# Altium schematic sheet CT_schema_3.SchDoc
size 572 x 500 mm
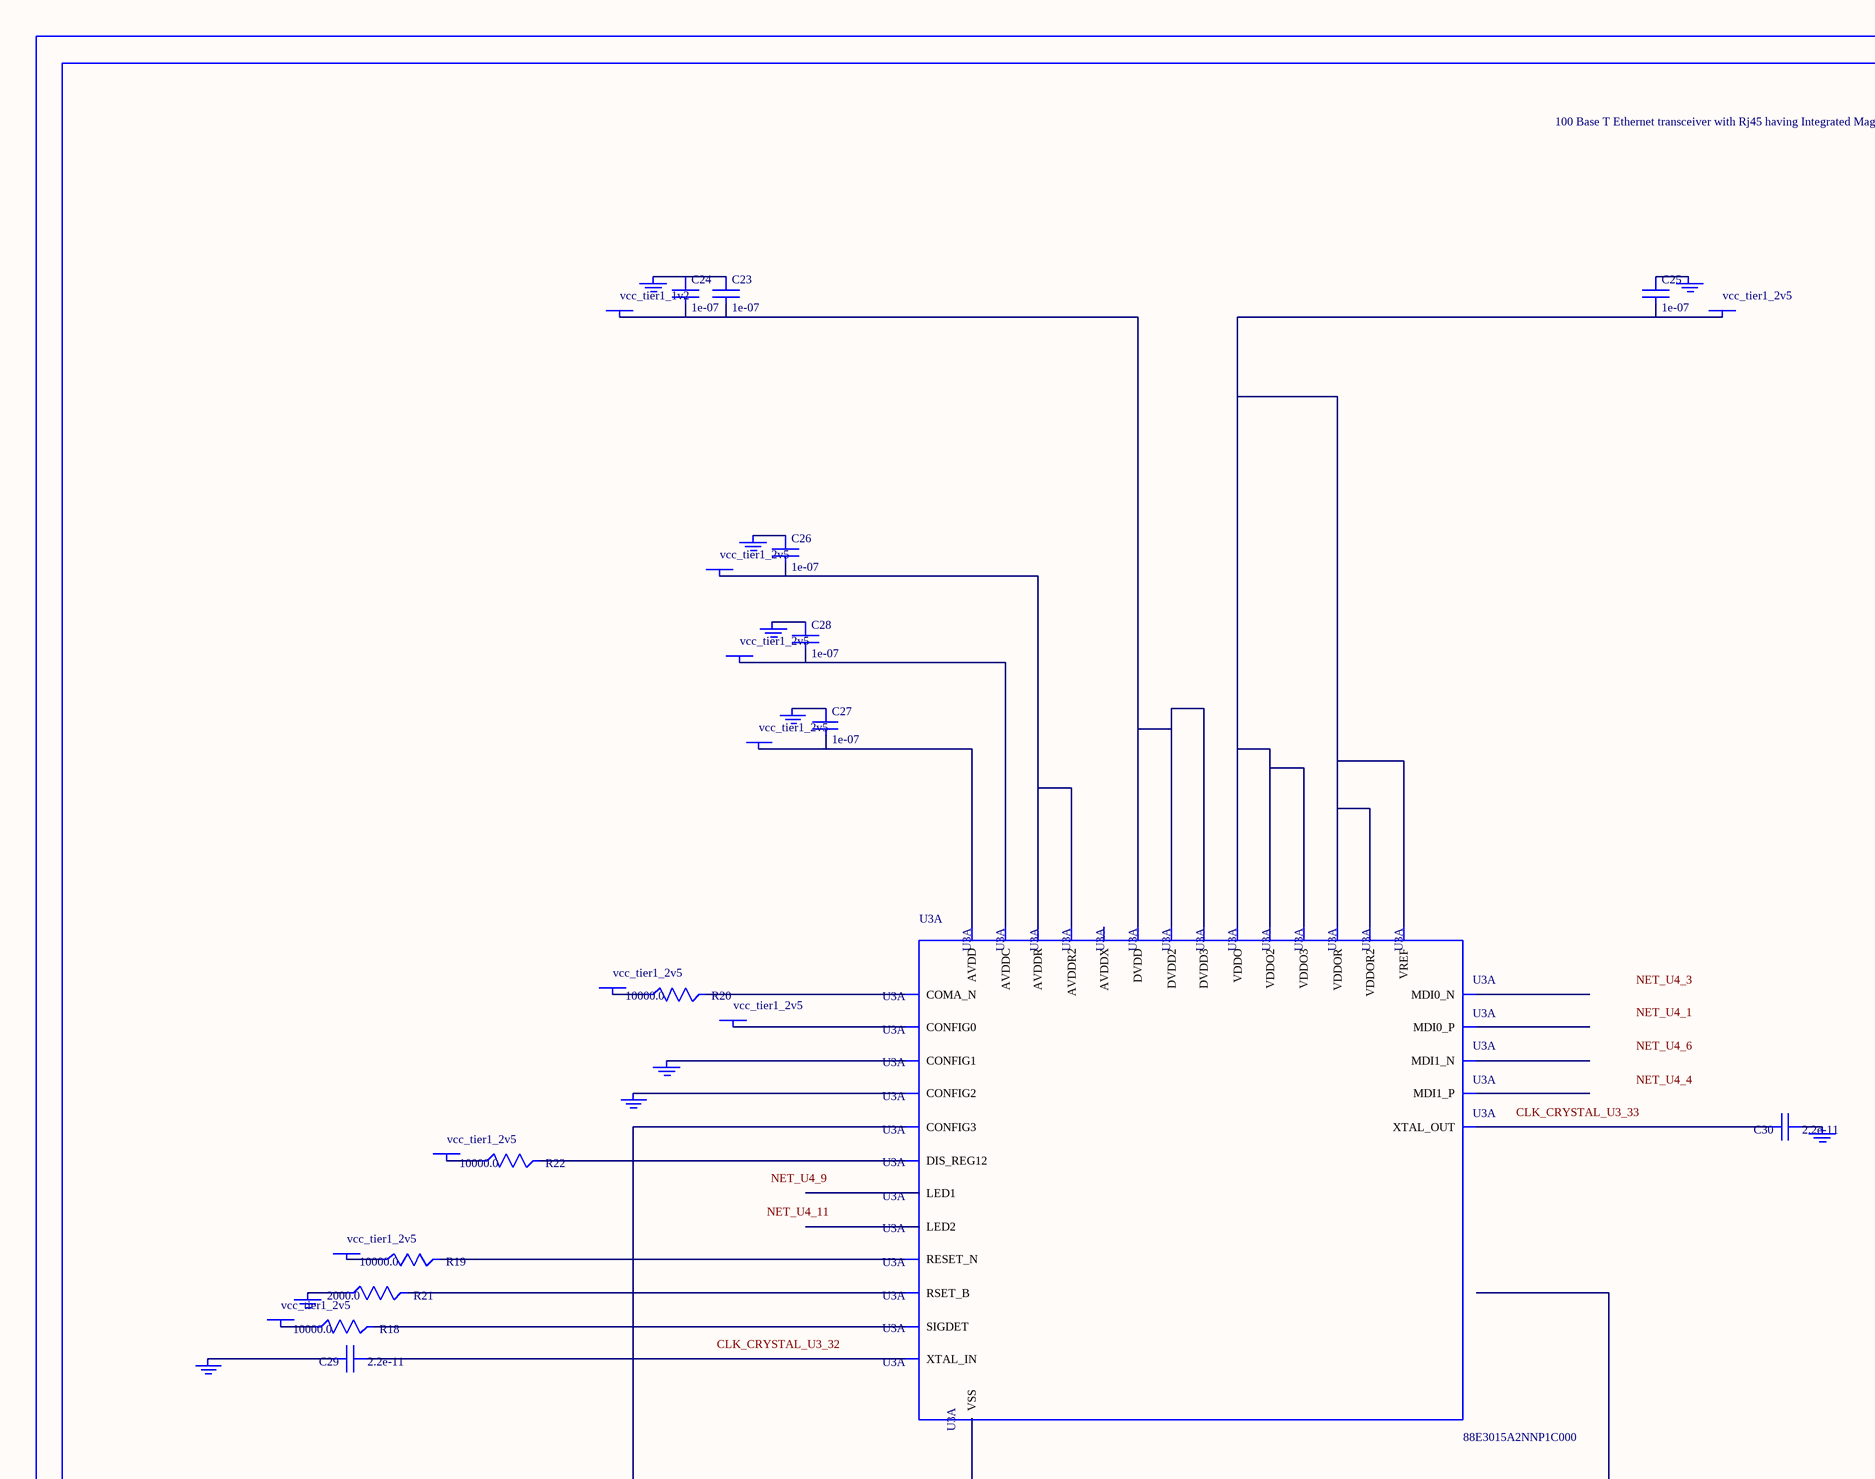
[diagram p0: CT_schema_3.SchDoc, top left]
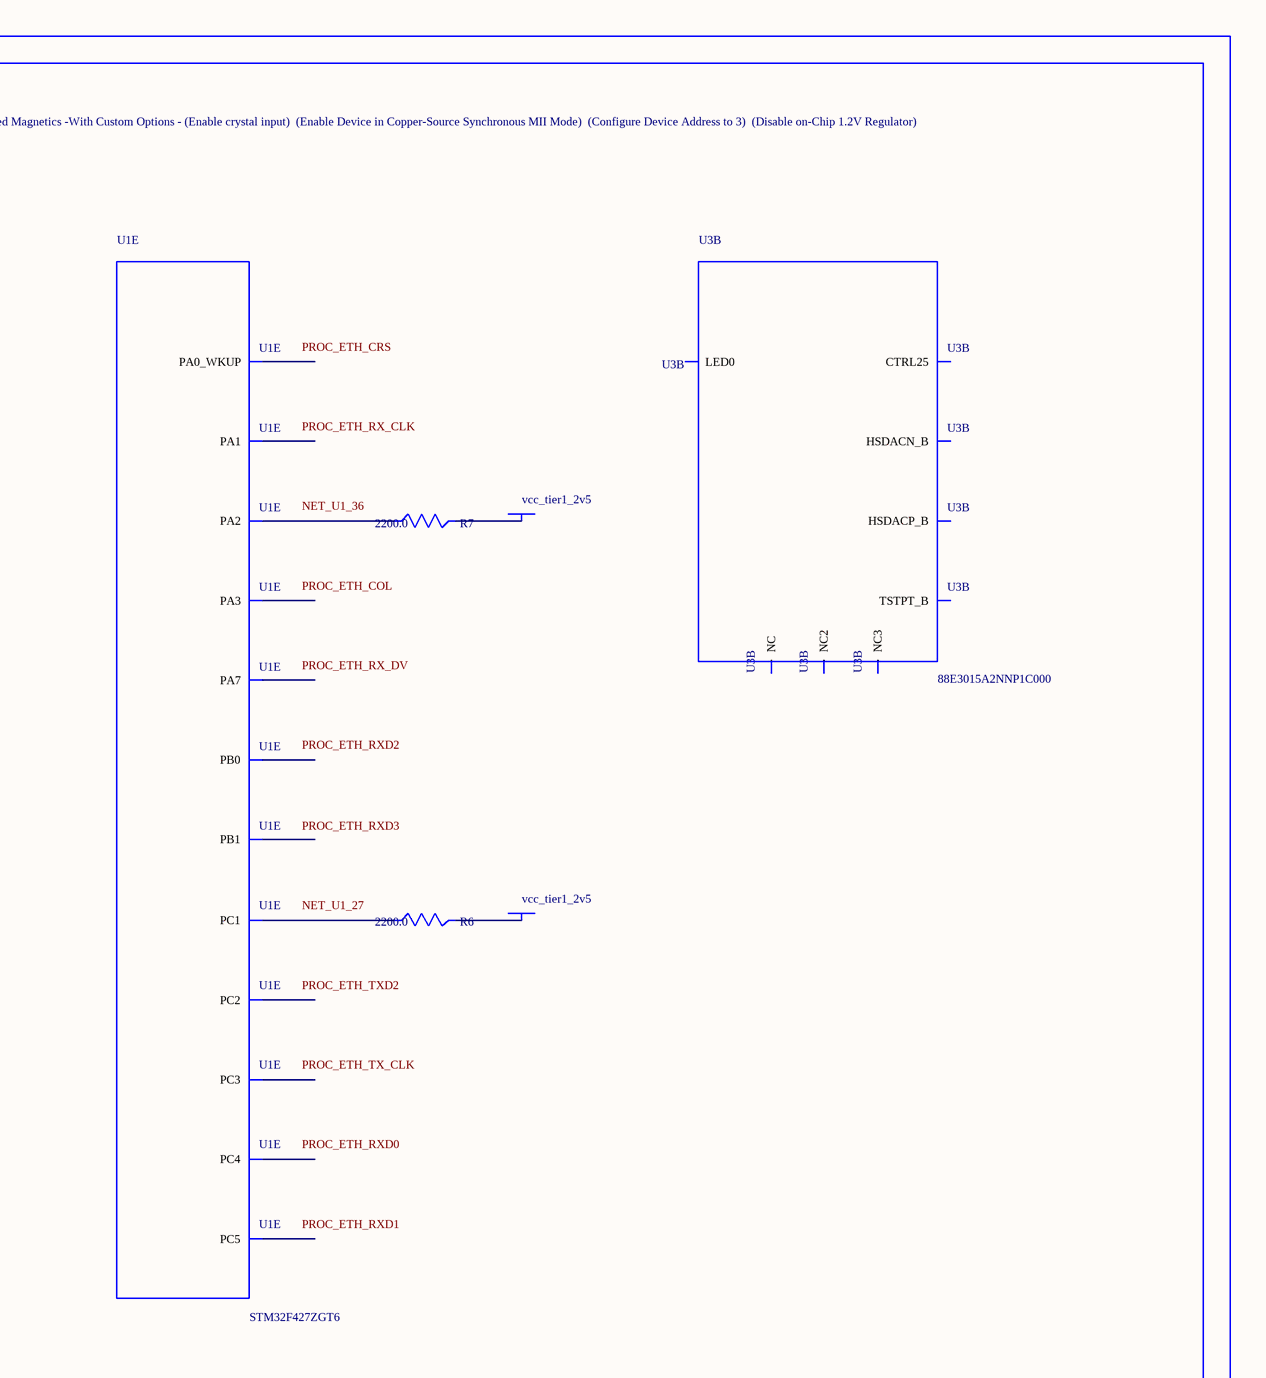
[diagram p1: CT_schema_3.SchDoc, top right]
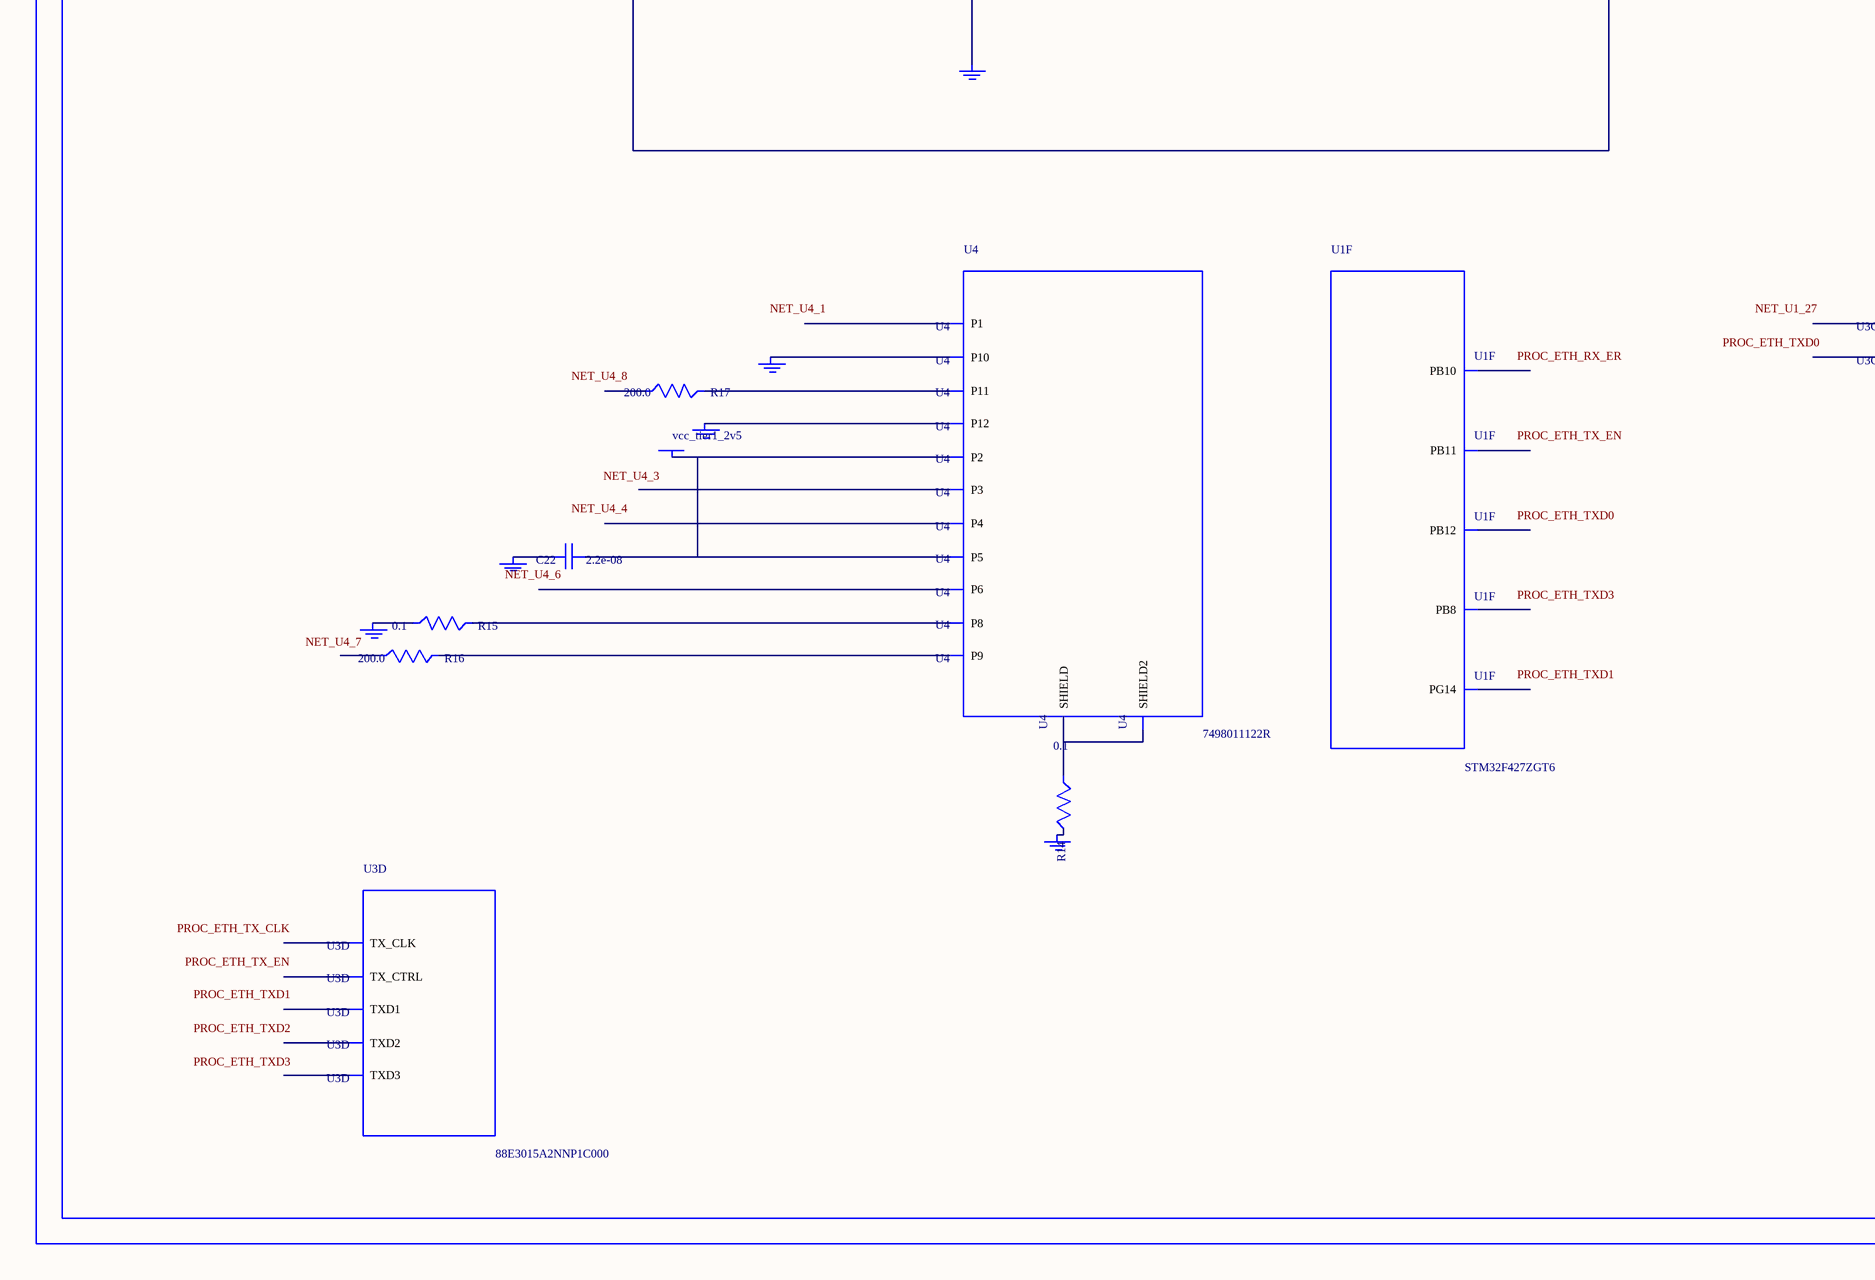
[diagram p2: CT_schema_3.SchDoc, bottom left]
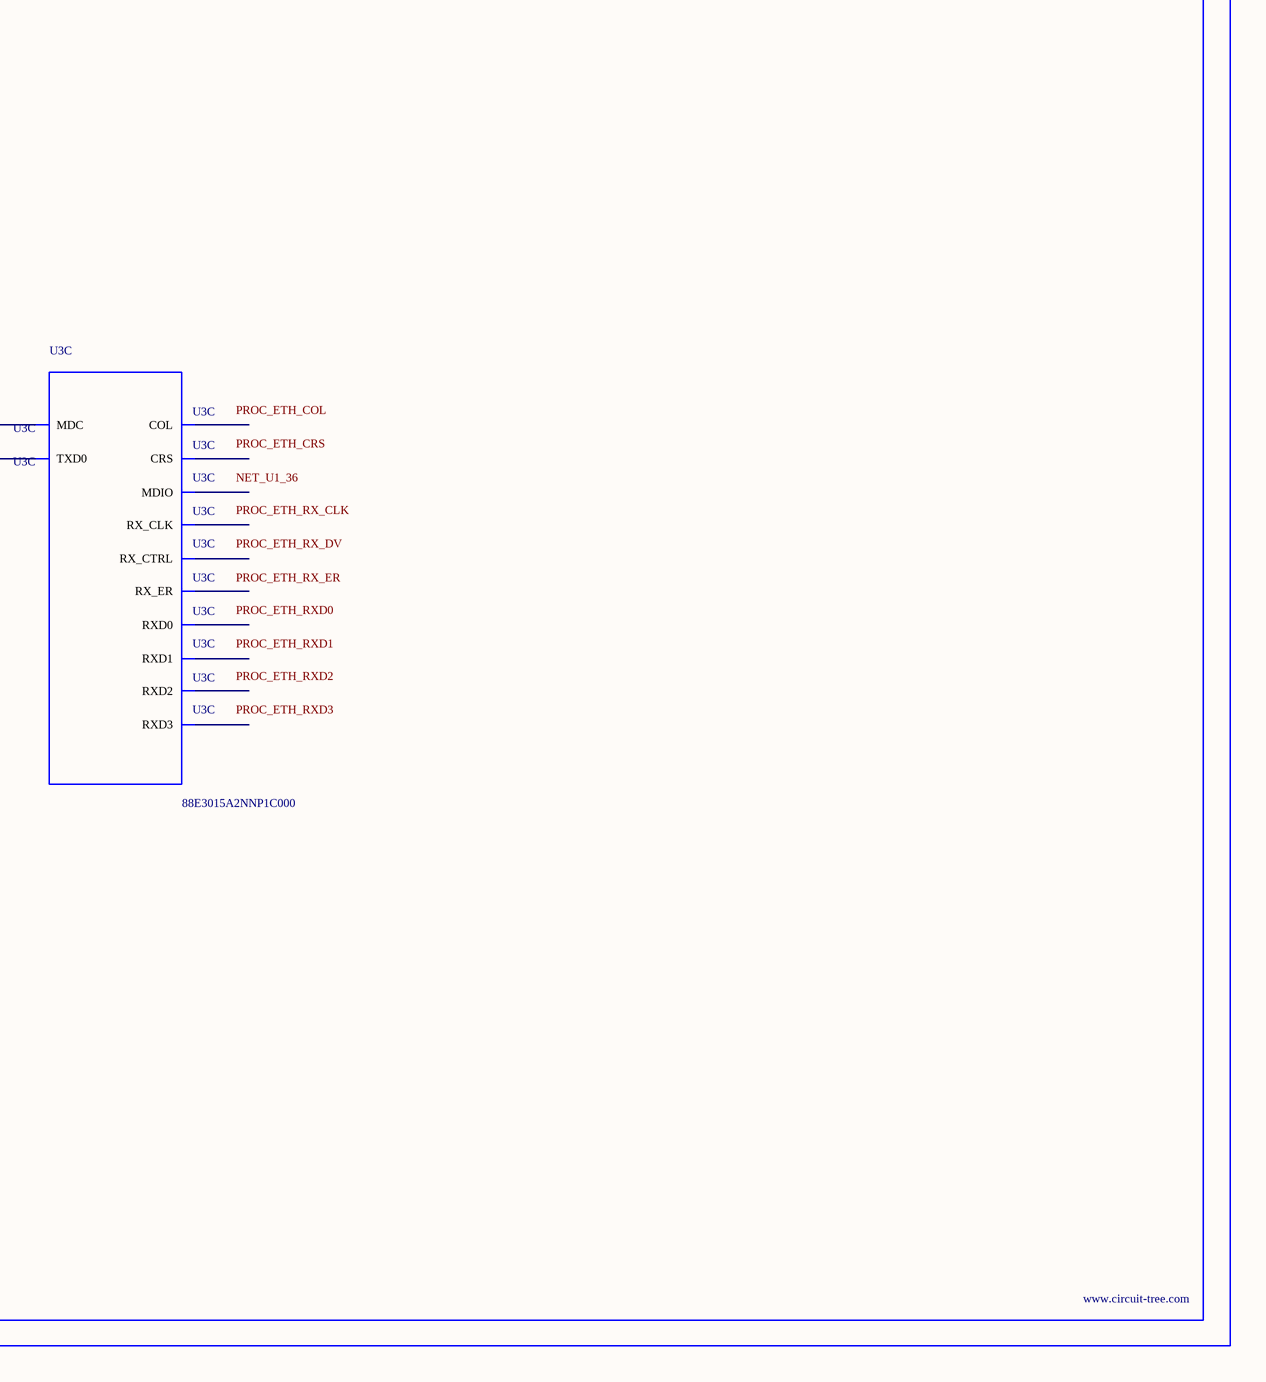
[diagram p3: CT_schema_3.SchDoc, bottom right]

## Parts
BORDER2  (no value)
C22  2.2e-08  [C0402]
C23  1e-07  [C0603]
C24  1e-07  [C0603]
C25  1e-07  [C0603]
C26  1e-07  [C0603]
C27  1e-07  [C0603]
C28  1e-07  [C0603]
C29  2.2e-11  [C0402]
C30  2.2e-11  [C0402]
GND_INSTANCE_2_0  (no value)
GND_INSTANCE_2_1  (no value)
GND_INSTANCE_2_2  (no value)
GND_INSTANCE_2_3  (no value)
GND_INSTANCE_2_4  (no value)
GND_INSTANCE_2_5  (no value)
GND_INSTANCE_2_6  (no value)
GND_INSTANCE_2_7  (no value)
GND_INSTANCE_2_8  (no value)
GND_INSTANCE_2_9  (no value)
GND_INSTANCE_2_10  (no value)
GND_INSTANCE_2_11  (no value)
GND_INSTANCE_2_12  (no value)
GND_INSTANCE_2_13  (no value)
GND_INSTANCE_2_14  (no value)
GND_INSTANCE_2_15  (no value)
POWER_INSTANCE_2_0  vcc_tier1_1v2
POWER_INSTANCE_2_1  vcc_tier1_2v5
POWER_INSTANCE_2_2  vcc_tier1_2v5
POWER_INSTANCE_2_3  vcc_tier1_2v5
POWER_INSTANCE_2_4  vcc_tier1_2v5
POWER_INSTANCE_2_5  vcc_tier1_2v5
POWER_INSTANCE_2_6  vcc_tier1_2v5
POWER_INSTANCE_2_7  vcc_tier1_2v5
POWER_INSTANCE_2_8  vcc_tier1_2v5
POWER_INSTANCE_2_9  vcc_tier1_2v5
POWER_INSTANCE_2_10  vcc_tier1_2v5
POWER_INSTANCE_2_11  vcc_tier1_2v5
POWER_INSTANCE_2_12  vcc_tier1_2v5
R6  2200.0  [R0603]
R7  2200.0  [R0603]
R14  0.1  [R0603]
R15  0.1  [R0603]
R16  200.0  [R0603]
R17  200.0  [R0603]
R18  10000.0  [R0603]
R19  10000.0  [R0603]
R20  10000.0  [R0603]
R21  2000.0  [R0603]
R22  10000.0  [R0603]
U1  STM32F427ZGT6  [LQFP144]  (parts E,F of 12)
U3  88E3015A2NNP1C000  [88E3015A2NNP1C000]  (parts A,B,C,D of 4)
U4  7498011122R  [7498011122R]

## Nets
NetC22_1: C22.1 POWER_INSTANCE_2_12.0(PWR) U4.2(P2) U4.5(P5)
NetC22_2: C22.2 GND_INSTANCE_2_11.0(GND)
NetC23_1: C23.1 C24.1 GND_INSTANCE_2_2.0(GND)
NetC23_2: C23.2 C24.2 POWER_INSTANCE_2_0.0(PWR) U3.4(DVDD) U3.11(DVDD2) U3.34(DVDD3)
NetC25_1: C25.1 GND_INSTANCE_2_3.0(GND)
NetC25_2: C25.2 POWER_INSTANCE_2_1.0(PWR) U3.6(VDDO) U3.20(VDDO2) U3.36(VDDO3) U3.44(VDDOR) U3.48(VDDOR2) U3.49(VREF)
NetC26_1: C26.1 GND_INSTANCE_2_4.0(GND)
NetC26_2: C26.2 POWER_INSTANCE_2_4.0(PWR) U3.12(AVDDR) U3.13(AVDDR2)
NetC27_1: C27.1 GND_INSTANCE_2_5.0(GND)
NetC27_2: C27.2 POWER_INSTANCE_2_6.0(PWR) U3.24(AVDD)
NetC28_1: C28.1 GND_INSTANCE_2_7.0(GND)
NetC28_2: C28.2 POWER_INSTANCE_2_7.0(PWR) U3.29(AVDDC)
NetC29_1: C29.1 U3.32(XTAL_IN)
NetC29_2: C29.2 GND_INSTANCE_2_8.0(GND)
NetC30_1: C30.1 GND_INSTANCE_2_9.0(GND)
NetC30_2: C30.2 U3.33(XTAL_OUT)
NetGND_INSTANCE_2_0_0: GND_INSTANCE_2_0.0(GND) U3.1(CONFIG1)
NetGND_INSTANCE_2_1_0: GND_INSTANCE_2_1.0(GND) U3.2(CONFIG2)
NetGND_INSTANCE_2_6_0: GND_INSTANCE_2_6.0(GND) R21.1
NetGND_INSTANCE_2_10_0: GND_INSTANCE_2_10.0(GND) U3.57(VSS)
NetGND_INSTANCE_2_12_0: GND_INSTANCE_2_12.0(GND) R15.1
NetGND_INSTANCE_2_13_0: GND_INSTANCE_2_13.0(GND) U4.10(P10)
NetGND_INSTANCE_2_14_0: GND_INSTANCE_2_14.0(GND) U4.12(P12)
NetGND_INSTANCE_2_15_0: GND_INSTANCE_2_15.0(GND) R14.2
NetPOWER_INSTANCE_2_2_0: POWER_INSTANCE_2_2.0(PWR) R19.1
NetPOWER_INSTANCE_2_3_0: POWER_INSTANCE_2_3.0(PWR) R22.1
NetPOWER_INSTANCE_2_5_0: POWER_INSTANCE_2_5.0(PWR) R18.1
NetPOWER_INSTANCE_2_8_0: POWER_INSTANCE_2_8.0(PWR) R20.1
NetPOWER_INSTANCE_2_9_0: POWER_INSTANCE_2_9.0(PWR) U3.56(CONFIG0)
NetPOWER_INSTANCE_2_10_0: POWER_INSTANCE_2_10.0(PWR) R6.2
NetPOWER_INSTANCE_2_11_0: POWER_INSTANCE_2_11.0(PWR) R7.2
NetR6_1: R6.1 U1.27(PC1)
NetR7_1: R7.1 U1.36(PA2)
NetR14_1: R14.1 U4.13(SHIELD) U4.14(SHIELD2)
NetR15_2: R15.2 U4.8(P8)
NetR16_2: R16.2 U4.9(P9)
NetR17_2: R17.2 U4.11(P11)
NetR18_2: R18.2 U3.16(SIGDET)
NetR19_2: R19.2 U3.9(RESET_N)
NetR20_2: R20.2 U3.39(COMA_N)
NetR21_2: R21.2 U3.28(RSET_B)
NetR22_2: R22.2 U3.10(DIS_REG12)

Not connected (* = marked no-connect by the designer): R16 1; R17 1; U1 28(PC2) 29(PC3) 34(PA0_WKUP) 35(PA1) 37(PA3) 43(PA7) 44(PC4) 45(PC5) 46(PB0) 47(PB1) 69(PB10) 70(PB11) 73(PB12) 129(PG14) 139(PB8); U3 3(CONFIG3) 5(LED0) 7(LED1) 8(LED2) 14(AVDDX) 15(CTRL25) 17(RX_ER) 18(CRS) 19(COL) 21(NC) 22(MDI1_N) 23(MDI1_P) 25(MDI0_N) 26(MDI0_P) 27(TSTPT_B) 30(HSDACN_B) 31(HSDACP_B) 35(MDIO) 37(NC2) 38(MDC) 40(NC3) 41(RX_CTRL) 42(RXD0) 43(RXD1) 45(RX_CLK) 46(RXD2) 47(RXD3) 50(TXD0) 51(TXD1) 52(TX_CLK) 53(TXD2) 54(TXD3) 55(TX_CTRL); U4 1(P1) 3(P3) 4(P4) 6(P6)

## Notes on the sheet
- Labels drawn without touching a wire or pin: CLK_CRYSTAL_U3_32, CLK_CRYSTAL_U3_33, NET_U1_27, NET_U1_36, NET_U4_1, NET_U4_3, NET_U4_4, NET_U4_6, NET_U4_7, NET_U4_8, NET_U4_9, NET_U4_11, PROC_ETH_COL, PROC_ETH_CRS, PROC_ETH_RX_CLK, PROC_ETH_RX_DV, PROC_ETH_RX_ER, PROC_ETH_RXD0, PROC_ETH_RXD1, PROC_ETH_RXD2, PROC_ETH_RXD3, PROC_ETH_TX_CLK, PROC_ETH_TX_EN, PROC_ETH_TXD0, PROC_ETH_TXD1, PROC_ETH_TXD2, PROC_ETH_TXD3

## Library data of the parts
BORDER2 = BORDER_PAGE2
C22 = C0402C223K3RAC
C23-C28 = 06035C104K4Z2A
C29 C30 = C0402C220K3RAC
GND_INSTANCE_2_0-GND_INSTANCE_2_15 = GND
POWER_INSTANCE_2_0-POWER_INSTANCE_2_12 = PWR
R6 R7 = RC0603JR-072K2L
R14 R15 = ERJ-3RSFR10V
R16 R17 = RC0603JR-07200RL
R18-R20 R22 = RC0603JR-0710KL
R21 = RC0603JR-072KL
